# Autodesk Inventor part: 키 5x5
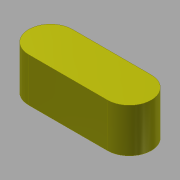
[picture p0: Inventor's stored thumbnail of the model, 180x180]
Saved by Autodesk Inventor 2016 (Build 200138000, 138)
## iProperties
Created: 2014-10
Part Number: 키 5x5
Document SubType Name: Modeling
Designer: KYOUNG IL JANG
Density: 7.86 g/cm^3
Mass: 2.54015 g
Surface Area: 2.9781 cm^2
Volume: 0.323175 cm^3
Material: 강철, 연강
Appearance: 노란색
Author: SeoGD™ [www.esajin.kr]
Revision Number: 1
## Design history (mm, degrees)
sketch "스케치1"
  geometry: L1 (-4.5, -2.5)-(4.5, -2.5); L2 (4.5, 2.5)-(-4.5, 2.5); A1 r 2.5 centre (4.5, 0) between (4.5, -2.5) and (4.5, 2.5); A2 r 2.5 centre (-4.5, 0) between (-4.5, 2.5) and (-4.5, -2.5); 2 further points
  constraints: 4 end point, 4 point on circle, 4 tangent, 2 centre point, 1 horizontal, 1 horizontal alignment, 1 midpoint, 1 parallel, 1 vertical alignment
  dimensions: "d0" = 5 distance between parallel lines of L1 L2; "d1" = 14 dimension on A1 A2
extrude "돌출1" new body sketch "스케치1" stored distance "d2" = 5; taper "d3" = 0 deg
node "솔리드1"
